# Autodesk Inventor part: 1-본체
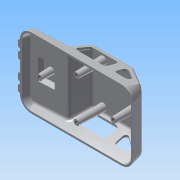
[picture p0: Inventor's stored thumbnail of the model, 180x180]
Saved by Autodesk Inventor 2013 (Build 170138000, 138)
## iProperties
Created: 2015-05
Part Number: 1-본체
Material: ABS 플라스틱
Document SubType Name: Modeling
Designer: Administrator
Density: 7.85 g/cm^3
Mass: 241.072 g
Surface Area: 306.17 cm^2
Volume: 30.7098 cm^3
Author: Administrator
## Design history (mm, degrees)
sketch "스케치1"
  geometry: L1 (-61, 0)-(61, 0); L2 (-61, 0)-(-58.588, 9); L3 (-19, 11.075)-(-13.661, 31); L4 (-13.661, 31)-(31, 31); L5 (31, 31)-(61, 11); L6 (57.412, 13.392)-(61, 0); L7 (-58.588, 9)-(-19, 11.075); L8 (61, 0)-(61, 38); 2 further points
  constraints: 16 end point, 2 point on line, 1 coincident, 1 horizontal, 1 midpoint, 1 parallel, 1 perpendicular
  dimensions: "d0" = 122 distance of L1.start L1.end; "d2" = 105 deg angle of L2 L1; "d5" = 105 deg angle of L1 L6; "d11" = 42 horizontal distance of L3.start L1.start; "d12" = 31 distance between parallel lines of L1 L4; "d13" = 30 horizontal distance of L1.end L4.end; "d14" = 20 vertical distance of L4.end L5.end; "d15" = 9 distance from line of L1 L2.end; "d33" = 3 deg angle of L1 L7
extrude "돌출1" new body sketch "스케치1" stored distance "d16" = 76; taper "d17" = 0 deg
sketch "스케치2"
  geometry: L1 (8.121, 51)-(28.121, 51); L2 (28.121, 51)-(28.121, 25); L3 (28.121, 25)-(8.121, 25); L4 (8.121, 25)-(8.121, 51); L5 (8.121, 51)-(28.121, 25); L6 (28.121, 51)-(8.121, 25); L7 (-2.879, 0)-(-2.879, 76) reference; 3 further points
  constraints: 12 end point, 3 midpoint, 2 parallel, 1 horizontal, 1 horizontal alignment, 1 perpendicular
  dimensions: "d18" = 20 distance of L1.start L1.end; "d20" = 26 distance of L1.end L2.end; "d21" = 11 distance between parallel lines of L4 L7
extrude "돌출2" join sketch "스케치2" distance "d22" = 5; taper "d23" = -20 deg
fillet "모깎기1" dims "d60" = 12
node "작업 평면4"
sketch "스케치7"
  geometry: L1 (0, -38)-(0, -26) reference; L2 (0, 26)-(0, 38) reference; L3 (31, -38)-(23.476, -38) reference; L4 (23.476, 38)-(31, 38) reference; L5 (0, 38)-(31, 29.694); L6 (31, -29.694)-(0, -38); L7 (31, -38)-(31, -29.694); L8 (31, -38)-(0, -38); L9 (31, 29.694)-(31, 38); L10 (0, 38)-(31, 38); 1 further point
  constraints: 12 end point, 3 perpendicular, 1 collinear, 1 point on line
  dimensions: "d62" = 105 deg angle of L2 L5; "d63" = 105 deg angle of L1 L6
extrude "돌출6" cut sketch "스케치7" stored distance "d64" = 5; taper "d65" = 0 deg
feature "쉘1" dims "d24" = 2
sketch "스케치5"
  geometry: L1 (-61, 0)-(61, 0) reference; L2 (57.412, 13.392)-(31, 31) reference; L3 (31, 31)-(-13.661, 31) reference; L4 (-13.661, 31)-(-19, 11.075) reference; L5 (-58.588, 9)-(-61, 0) reference; L6 (29.486, 20.394)-(29.486, 14); L7 (32.486, 11)-(42.078, 11); L8 (43.742, 16.496)-(34.15, 22.891); L9 (-12.832, 14.776)-(-10.42, 23.776); L10 (-7.522, 26)-(17.156, 26); L11 (20.156, 23)-(20.156, 14); L12 (17.156, 11)-(-9.934, 11); A1 r 3 centre (-7.522, 23) between (-7.522, 26) and (-10.42, 23.776); A2 r 3 centre (-9.934, 14) between (-12.832, 14.776) and (-9.934, 11); A3 r 3 centre (17.156, 23) between (20.156, 23) and (17.156, 26); A4 r 3 centre (17.156, 14) between (17.156, 11) and (20.156, 14); A5 r 3 centre (32.486, 20.394) between (34.15, 22.891) and (29.486, 20.394); A6 r 3 centre (32.486, 14) between (29.486, 14) and (32.486, 11); A7 r 3 centre (42.078, 14) between (42.078, 11) and (43.742, 16.496); 6 further points
  constraints: 14 end point, 14 point on circle, 14 tangent, 10 point on line, 7 centre point, 6 equal radius, 5 parallel, 2 perpendicular
  dimensions: "d39" = 15 distance of point (29.486, 26) point (29.486, 11); "d41" = 5 distance from line of point (29.486, 26) L3; "d42" = 5 distance between parallel lines of L8 L2; "d44" = 34 distance of point (20.156, 11) point (-13.844, 11); "d45" = 5 distance between parallel lines of L9 L4; "d46" = 5 distance between parallel lines of L3 L10; "d47" = 15 distance of point (20.156, 26) point (20.156, 11); "d48" = 3 radius of A1
extrude "돌출4" cut sketch "스케치5" stored distance "d49" = 5; taper "d50" = 0 deg
sketch "스케치3"
  geometry: L1 (122, -76)-(122, 0) reference; C1 r 3 at (21, -38); C2 r 3 at (61, -16); C3 r 3 at (61, -60); C4 r 3 at (101, -38); 5 further points
  constraints: 4 centre point, 4 coincident, 3 equal radius, 3 vertical alignment, 2 horizontal alignment
  dimensions: "d25" = 6 diameter of C1; "d27" = 40 horizontal distance of C2.centre C1.centre; "d28" = 40 horizontal distance of C2.centre C4.centre; "d29" = 21 distance from line of L1 C4.centre (derived); "d30" = 6 diameter of C2 (derived); "d31" = 22 distance of C3.centre point (61, -38); "d32" = 22 distance of point (61, -38) C2.centre
extrude "돌출3" join sketch "스케치3" stored distance "d34" = 5; taper "d35" = 2 deg
node "작업 평면1"
sketch "스케치4"
  geometry: 1 further point
node "작업 평면3"
sketch "스케치6"
  geometry: A1 r 4 centre (0, -21) between (0, -25) and (0, -17); A2 r 4 centre (0, -10) between (0, -14) and (0, -6); A3 r 4 centre (0, 10) between (0, 6) and (0, 14); A4 r 4 centre (0, 21) between (0, 17) and (0, 25); 5 further points
  constraints: 8 point on circle, 4 centre point, 3 equal radius, 13 other
  dimensions: "d52" = 8 diameter of A1; "d54" = 11 distance of A2.centre A1.centre; "d55" = 10 distance of point (0, 0) A2.centre; "d56" = 10 distance of point (0, 0) A3.centre; "d57" = 11 distance of A4.centre A3.centre
extrude "돌출5" join sketch "스케치6" stored distance "d58" = 5; taper "d59" = 0 deg
fillet "모깎기2" dims "d66" = 3
fillet "모깎기3" dims "d67" = 3
fillet "모깎기4" dims "d68" = 3
fillet "모깎기5" dims "d69" = 3
fillet "모깎기6" dims "d70" = 3
fillet "모깎기7" dims "d71" = 3
hole "구멍1" sketch "스케치3" diameter "d72" = 3.242; stored, may be unused: countersink angle "d76" = 90 deg, drill point angle "d78" = 118 deg; dims "d73" = 9, "d74" = 4, "d75" = 2, "d77" = 11
chamfer "모따기1" distance "d79" = 1; stored, may be unused: second distance "d80" = 2, angle "d81" = 45 deg
sketch "스케치8"
  geometry: L1 (72.359, -1.392)-(72.359, -53.392) reference; 2 further points
  constraints: 1 horizontal alignment, 1 other
  dimensions: "d82" = 50 distance from line of L1 point (22.359, -27.392)
feature "엠보싱1" sketch "스케치8" dims "d23" = -20 deg, "d83" = 0.5, "d84" = 0
node "솔리드1"
other parameters: "d36" = -3, "d51" = -63, "d61" = 0
